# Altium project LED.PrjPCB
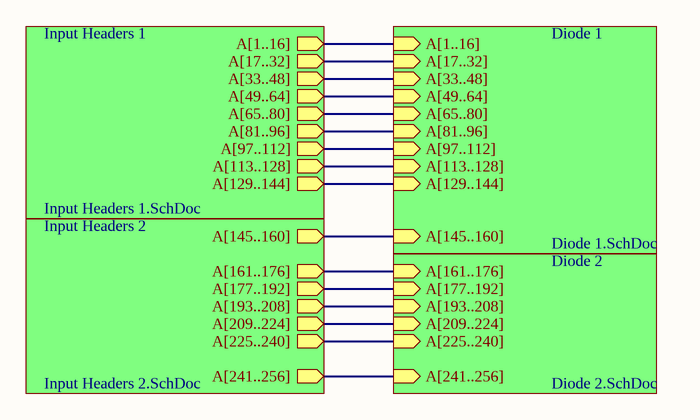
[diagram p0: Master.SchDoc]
5 sheets, 272 parts. Net scope: hierarchical (ports join the sheet entries above them; power ports are global).
Board file: LED Board.PcbDoc
Sheets:
  Master.SchDoc
    Input Headers 1 = Input Headers 1.SchDoc
    Input Headers 2 = Input Headers 2.SchDoc
    Diode 1 = Diode 1.SchDoc
    Diode 2 = Diode 2.SchDoc

## Sheet Master.SchDoc
size A

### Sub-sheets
Diode 1 = Diode 1.SchDoc: A[1..16] (in), A[17..32] (in), A[33..48] (in), A[49..64] (in), A[65..80] (in), A[145..160] (in), A[81..96] (in), A[97..112] (in), A[113..128] (in), A[129..144] (in)
Diode 2 = Diode 2.SchDoc: A[225..240] (in), A[161..176] (in), A[177..192] (in), A[193..208] (in), A[209..224] (in), A[241..256] (in)
Input Headers 1 = Input Headers 1.SchDoc: A[1..16] (out), A[17..32] (out), A[33..48] (out), A[49..64] (out), A[65..80] (out), A[81..96] (out), A[97..112] (out), A[113..128] (out), A[129..144] (out)
Input Headers 2 = Input Headers 2.SchDoc: A[145..160] (out), A[225..240] (out), A[161..176] (out), A[177..192] (out), A[193..208] (out), A[209..224] (out), A[241..256] (out)

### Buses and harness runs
bus sheet Diode 1/A[1..16] = sheet Input Headers 1/A[1..16]
bus sheet Diode 1/A[17..32] = sheet Input Headers 1/A[17..32]
bus sheet Diode 1/A[33..48] = sheet Input Headers 1/A[33..48]
bus sheet Diode 1/A[49..64] = sheet Input Headers 1/A[49..64]
bus sheet Diode 1/A[65..80] = sheet Input Headers 1/A[65..80]
bus sheet Diode 1/A[81..96] = sheet Input Headers 1/A[81..96]
bus sheet Diode 1/A[97..112] = sheet Input Headers 1/A[97..112]
bus sheet Diode 1/A[113..128] = sheet Input Headers 1/A[113..128]
bus sheet Diode 1/A[129..144] = sheet Input Headers 1/A[129..144]
bus sheet Diode 1/A[145..160] = sheet Input Headers 2/A[145..160]
bus sheet Diode 2/A[161..176] = sheet Input Headers 2/A[161..176]
bus sheet Diode 2/A[177..192] = sheet Input Headers 2/A[177..192]
bus sheet Diode 2/A[193..208] = sheet Input Headers 2/A[193..208]
bus sheet Diode 2/A[209..224] = sheet Input Headers 2/A[209..224]
bus sheet Diode 2/A[225..240] = sheet Input Headers 2/A[225..240]
bus sheet Diode 2/A[241..256] = sheet Input Headers 2/A[241..256]

## Sheet Input Headers 1.SchDoc: Input Headers 1
size A; DocumentNumber: 1; SheetNumber: 4
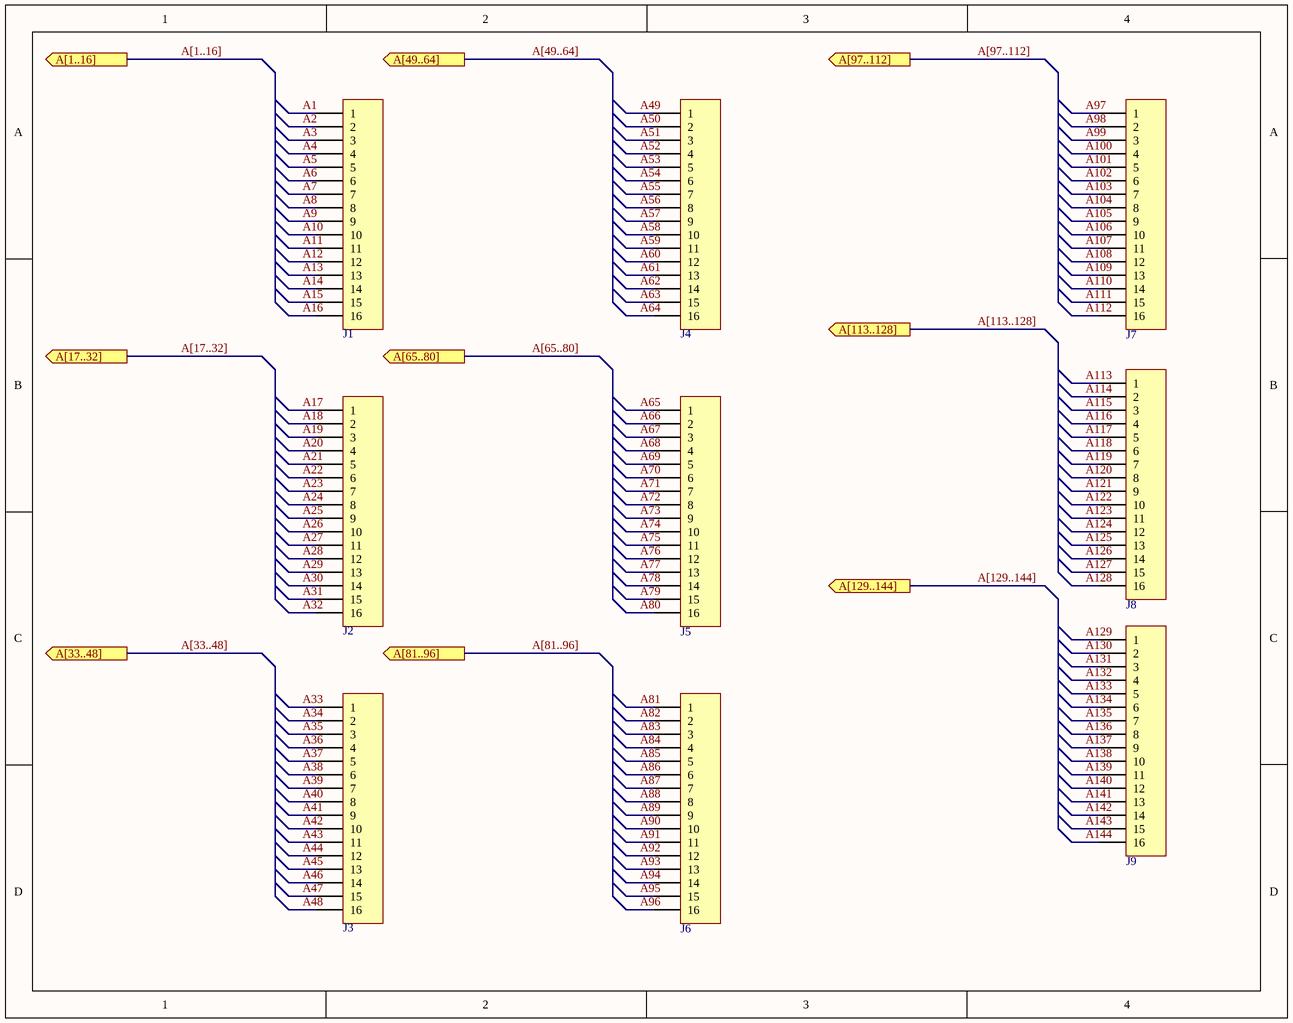
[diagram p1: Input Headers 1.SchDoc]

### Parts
J1  HDR2X8  [HDR2X8]  (value not drawn)
J2  HDR2X8  [HDR2X8]  (value not drawn)
J3  HDR2X8  [HDR2X8]  (value not drawn)
J4  HDR2X8  [HDR2X8]  (value not drawn)
J5  HDR2X8  [HDR2X8]  (value not drawn)
J6  HDR2X8  [HDR2X8]  (value not drawn)
J7  HDR2X8  [HDR2X8]  (value not drawn)
J8  HDR2X8  [HDR2X8]  (value not drawn)
J9  HDR2X8  [HDR2X8]  (value not drawn)

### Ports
A[1..16] (out), A[17..32] (out), A[33..48] (out), A[49..64] (out), A[65..80] (out), A[81..96] (out), A[97..112] (out), A[113..128] (out), A[129..144] (out)

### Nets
A1: J1.1
A2: J1.2
A3: J1.3
A4: J1.4
A5: J1.5
A6: J1.6
A7: J1.7
A8: J1.8
A9: J1.9
A10: J1.10
A11: J1.11
A12: J1.12
A13: J1.13
A14: J1.14
A15: J1.15
A16: J1.16
A17: J2.1
A18: J2.2
A19: J2.3
A20: J2.4
A21: J2.5
A22: J2.6
A23: J2.7
A24: J2.8
A25: J2.9
A26: J2.10
A27: J2.11
A28: J2.12
A29: J2.13
A30: J2.14
A31: J2.15
A32: J2.16
A33: J3.1
A34: J3.2
A35: J3.3
A36: J3.4
A37: J3.5
A38: J3.6
A39: J3.7
A40: J3.8
A41: J3.9
A42: J3.10
A43: J3.11
A44: J3.12
A45: J3.13
A46: J3.14
A47: J3.15
A48: J3.16
A49: J4.1
A50: J4.2
A51: J4.3
A52: J4.4
A53: J4.5
A54: J4.6
A55: J4.7
A56: J4.8
A57: J4.9
A58: J4.10
A59: J4.11
A60: J4.12
A61: J4.13
A62: J4.14
A63: J4.15
A64: J4.16
A65: J5.1
A66: J5.2
A67: J5.3
A68: J5.4
A69: J5.5
A70: J5.6
A71: J5.7
A72: J5.8
A73: J5.9
A74: J5.10
A75: J5.11
A76: J5.12
A77: J5.13
A78: J5.14
A79: J5.15
A80: J5.16
A81: J6.1
A82: J6.2
A83: J6.3
A84: J6.4
A85: J6.5
A86: J6.6
A87: J6.7
A88: J6.8
A89: J6.9
A90: J6.10
A91: J6.11
A92: J6.12
A93: J6.13
A94: J6.14
A95: J6.15
A96: J6.16
A97: J7.1
A98: J7.2
A99: J7.3
A100: J7.4
A101: J7.5
A102: J7.6
A103: J7.7
A104: J7.8
A105: J7.9
A106: J7.10
A107: J7.11
A108: J7.12
A109: J7.13
A110: J7.14
A111: J7.15
A112: J7.16
A113: J8.1
A114: J8.2
A115: J8.3
A116: J8.4
A117: J8.5
A118: J8.6
A119: J8.7
A120: J8.8
A121: J8.9
A122: J8.10
A123: J8.11
A124: J8.12
A125: J8.13
A126: J8.14
A127: J8.15
A128: J8.16
A129: J9.1
A130: J9.2
A131: J9.3
A132: J9.4
A133: J9.5
A134: J9.6
A135: J9.7
A136: J9.8
A137: J9.9
A138: J9.10
A139: J9.11
A140: J9.12
A141: J9.13
A142: J9.14
A143: J9.15
A144: J9.16

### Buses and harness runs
bus A[1..16] = port A[1..16]
bus A[17..32] = port A[17..32]
bus A[33..48] = port A[33..48]
bus A[49..64] = port A[49..64]
bus A[65..80] = port A[65..80]
bus A[81..96] = port A[81..96]
bus A[97..112] = port A[97..112]
bus A[113..128] = port A[113..128]
bus A[129..144] = port A[129..144]

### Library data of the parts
J1-J9 = MHDR1X16: Header, 16-Pin; Manufacturer: Generic Components; Class I: Connector

## Sheet Input Headers 2.SchDoc: Input Headers 2
size A; DocumentNumber: 1; SheetNumber: 5
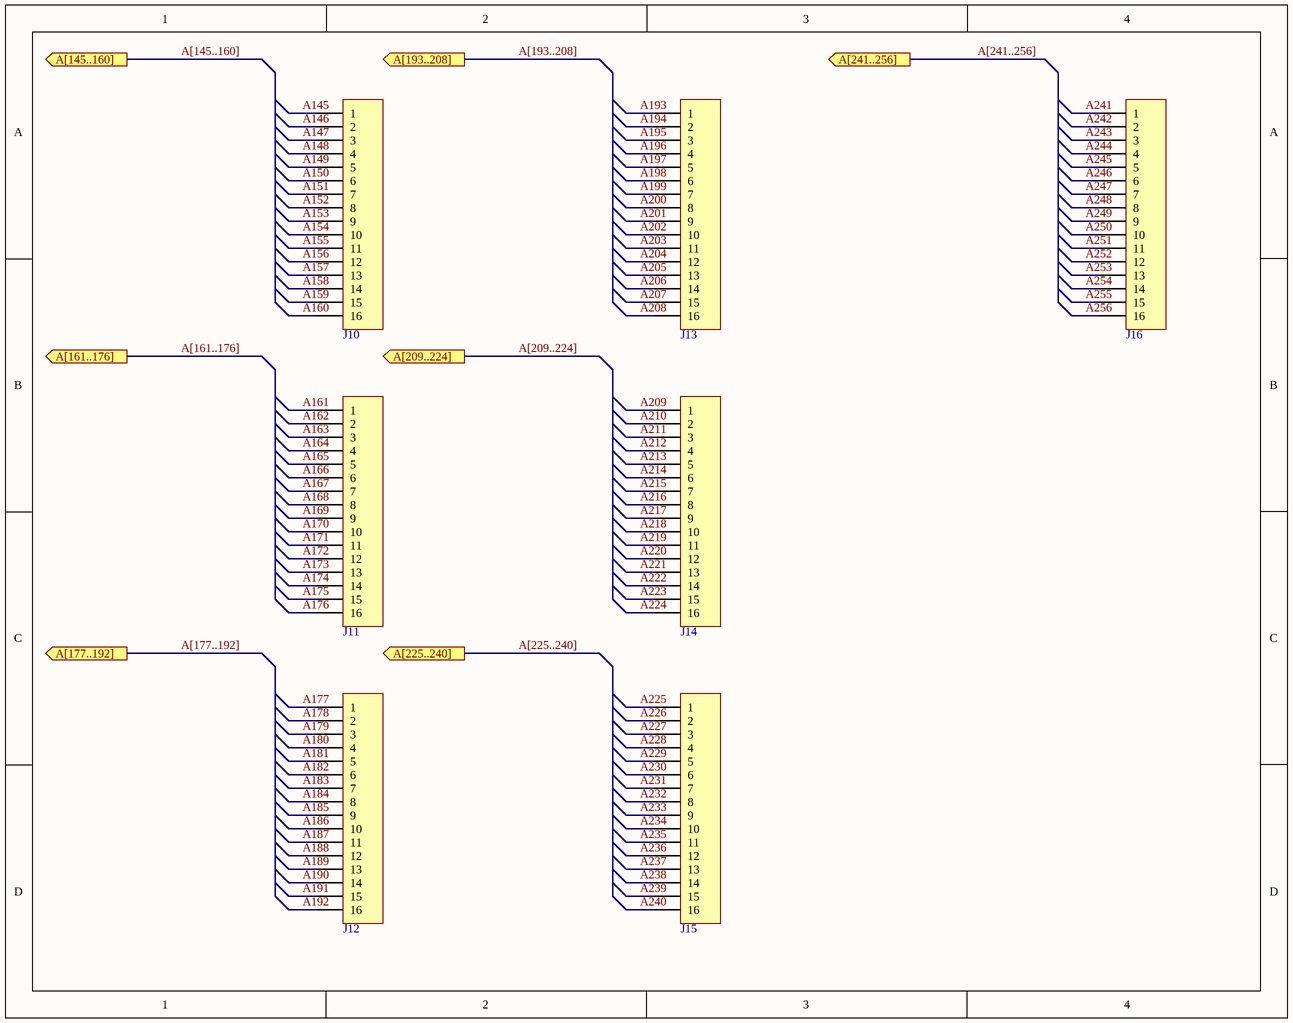
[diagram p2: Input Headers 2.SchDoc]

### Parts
J10  HDR2X8  [HDR2X8]  (value not drawn)
J11  HDR2X8  [HDR2X8]  (value not drawn)
J12  HDR2X8  [HDR2X8]  (value not drawn)
J13  HDR2X8  [HDR2X8]  (value not drawn)
J14  HDR2X8  [HDR2X8]  (value not drawn)
J15  HDR2X8  [HDR2X8]  (value not drawn)
J16  HDR2X8  [HDR2X8]  (value not drawn)

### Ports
A[145..160] (out), A[161..176] (out), A[177..192] (out), A[193..208] (out), A[209..224] (out), A[225..240] (out), A[241..256] (out)

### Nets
A145: J10.1
A146: J10.2
A147: J10.3
A148: J10.4
A149: J10.5
A150: J10.6
A151: J10.7
A152: J10.8
A153: J10.9
A154: J10.10
A155: J10.11
A156: J10.12
A157: J10.13
A158: J10.14
A159: J10.15
A160: J10.16
A161: J11.1
A162: J11.2
A163: J11.3
A164: J11.4
A165: J11.5
A166: J11.6
A167: J11.7
A168: J11.8
A169: J11.9
A170: J11.10
A171: J11.11
A172: J11.12
A173: J11.13
A174: J11.14
A175: J11.15
A176: J11.16
A177: J12.1
A178: J12.2
A179: J12.3
A180: J12.4
A181: J12.5
A182: J12.6
A183: J12.7
A184: J12.8
A185: J12.9
A186: J12.10
A187: J12.11
A188: J12.12
A189: J12.13
A190: J12.14
A191: J12.15
A192: J12.16
A193: J13.1
A194: J13.2
A195: J13.3
A196: J13.4
A197: J13.5
A198: J13.6
A199: J13.7
A200: J13.8
A201: J13.9
A202: J13.10
A203: J13.11
A204: J13.12
A205: J13.13
A206: J13.14
A207: J13.15
A208: J13.16
A209: J14.1
A210: J14.2
A211: J14.3
A212: J14.4
A213: J14.5
A214: J14.6
A215: J14.7
A216: J14.8
A217: J14.9
A218: J14.10
A219: J14.11
A220: J14.12
A221: J14.13
A222: J14.14
A223: J14.15
A224: J14.16
A225: J15.1
A226: J15.2
A227: J15.3
A228: J15.4
A229: J15.5
A230: J15.6
A231: J15.7
A232: J15.8
A233: J15.9
A234: J15.10
A235: J15.11
A236: J15.12
A237: J15.13
A238: J15.14
A239: J15.15
A240: J15.16
A241: J16.1
A242: J16.2
A243: J16.3
A244: J16.4
A245: J16.5
A246: J16.6
A247: J16.7
A248: J16.8
A249: J16.9
A250: J16.10
A251: J16.11
A252: J16.12
A253: J16.13
A254: J16.14
A255: J16.15
A256: J16.16

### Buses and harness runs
bus A[145..160] = port A[145..160]
bus A[161..176] = port A[161..176]
bus A[177..192] = port A[177..192]
bus A[193..208] = port A[193..208]
bus A[209..224] = port A[209..224]
bus A[225..240] = port A[225..240]
bus A[241..256] = port A[241..256]

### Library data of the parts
J10-J16 = MHDR1X16: as J1 on sheet Input Headers 1

## Sheet Diode 1.SchDoc: LED Connections 1
size A; DocumentNumber: 1; SheetNumber: 2
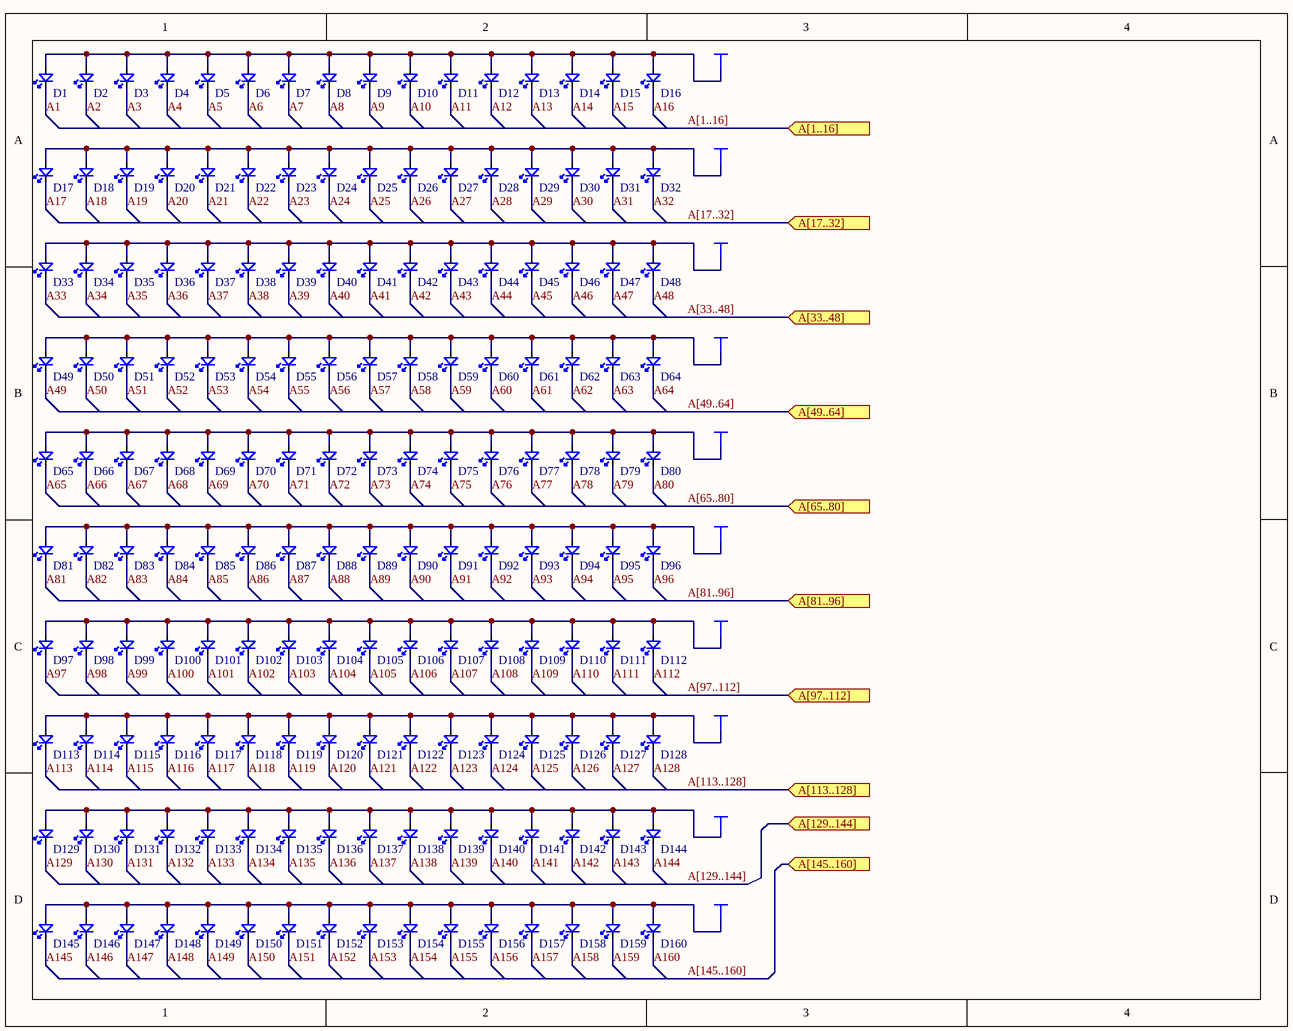
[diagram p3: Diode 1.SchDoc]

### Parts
D1  LED  [LED]  (value not drawn)
D2  LED  [LED]  (value not drawn)
D3  LED  [LED]  (value not drawn)
D4  LED  [LED]  (value not drawn)
D5  LED  [LED]  (value not drawn)
D6  LED  [LED]  (value not drawn)
D7  LED  [LED]  (value not drawn)
D8  LED  [LED]  (value not drawn)
D9  LED  [LED]  (value not drawn)
D10  LED  [LED]  (value not drawn)
D11  LED  [LED]  (value not drawn)
D12  LED  [LED]  (value not drawn)
D13  LED  [LED]  (value not drawn)
D14  LED  [LED]  (value not drawn)
D15  LED  [LED]  (value not drawn)
D16  LED  [LED]  (value not drawn)
D17  LED  [LED]  (value not drawn)
D18  LED  [LED]  (value not drawn)
D19  LED  [LED]  (value not drawn)
D20  LED  [LED]  (value not drawn)
D21  LED  [LED]  (value not drawn)
D22  LED  [LED]  (value not drawn)
D23  LED  [LED]  (value not drawn)
D24  LED  [LED]  (value not drawn)
D25  LED  [LED]  (value not drawn)
D26  LED  [LED]  (value not drawn)
D27  LED  [LED]  (value not drawn)
D28  LED  [LED]  (value not drawn)
D29  LED  [LED]  (value not drawn)
D30  LED  [LED]  (value not drawn)
D31  LED  [LED]  (value not drawn)
D32  LED  [LED]  (value not drawn)
D33  LED  [LED]  (value not drawn)
D34  LED  [LED]  (value not drawn)
D35  LED  [LED]  (value not drawn)
D36  LED  [LED]  (value not drawn)
D37  LED  [LED]  (value not drawn)
D38  LED  [LED]  (value not drawn)
D39  LED  [LED]  (value not drawn)
D40  LED  [LED]  (value not drawn)
D41  LED  [LED]  (value not drawn)
D42  LED  [LED]  (value not drawn)
D43  LED  [LED]  (value not drawn)
D44  LED  [LED]  (value not drawn)
D45  LED  [LED]  (value not drawn)
D46  LED  [LED]  (value not drawn)
D47  LED  [LED]  (value not drawn)
D48  LED  [LED]  (value not drawn)
D49  LED  [LED]  (value not drawn)
D50  LED  [LED]  (value not drawn)
D51  LED  [LED]  (value not drawn)
D52  LED  [LED]  (value not drawn)
D53  LED  [LED]  (value not drawn)
D54  LED  [LED]  (value not drawn)
D55  LED  [LED]  (value not drawn)
D56  LED  [LED]  (value not drawn)
D57  LED  [LED]  (value not drawn)
D58  LED  [LED]  (value not drawn)
D59  LED  [LED]  (value not drawn)
D60  LED  [LED]  (value not drawn)
D61  LED  [LED]  (value not drawn)
D62  LED  [LED]  (value not drawn)
D63  LED  [LED]  (value not drawn)
D64  LED  [LED]  (value not drawn)
D65  LED  [LED]  (value not drawn)
D66  LED  [LED]  (value not drawn)
D67  LED  [LED]  (value not drawn)
D68  LED  [LED]  (value not drawn)
D69  LED  [LED]  (value not drawn)
D70  LED  [LED]  (value not drawn)
D71  LED  [LED]  (value not drawn)
D72  LED  [LED]  (value not drawn)
D73  LED  [LED]  (value not drawn)
D74  LED  [LED]  (value not drawn)
D75  LED  [LED]  (value not drawn)
D76  LED  [LED]  (value not drawn)
D77  LED  [LED]  (value not drawn)
D78  LED  [LED]  (value not drawn)
D79  LED  [LED]  (value not drawn)
D80  LED  [LED]  (value not drawn)
D81  LED  [LED]  (value not drawn)
D82  LED  [LED]  (value not drawn)
D83  LED  [LED]  (value not drawn)
D84  LED  [LED]  (value not drawn)
D85  LED  [LED]  (value not drawn)
D86  LED  [LED]  (value not drawn)
D87  LED  [LED]  (value not drawn)
D88  LED  [LED]  (value not drawn)
D89  LED  [LED]  (value not drawn)
D90  LED  [LED]  (value not drawn)
D91  LED  [LED]  (value not drawn)
D92  LED  [LED]  (value not drawn)
D93  LED  [LED]  (value not drawn)
D94  LED  [LED]  (value not drawn)
D95  LED  [LED]  (value not drawn)
D96  LED  [LED]  (value not drawn)
D97  LED  [LED]  (value not drawn)
D98  LED  [LED]  (value not drawn)
D99  LED  [LED]  (value not drawn)
D100  LED  [LED]  (value not drawn)
D101  LED  [LED]  (value not drawn)
D102  LED  [LED]  (value not drawn)
D103  LED  [LED]  (value not drawn)
D104  LED  [LED]  (value not drawn)
D105  LED  [LED]  (value not drawn)
D106  LED  [LED]  (value not drawn)
D107  LED  [LED]  (value not drawn)
D108  LED  [LED]  (value not drawn)
D109  LED  [LED]  (value not drawn)
D110  LED  [LED]  (value not drawn)
D111  LED  [LED]  (value not drawn)
D112  LED  [LED]  (value not drawn)
D113  LED  [LED]  (value not drawn)
D114  LED  [LED]  (value not drawn)
D115  LED  [LED]  (value not drawn)
D116  LED  [LED]  (value not drawn)
D117  LED  [LED]  (value not drawn)
D118  LED  [LED]  (value not drawn)
D119  LED  [LED]  (value not drawn)
D120  LED  [LED]  (value not drawn)
D121  LED  [LED]  (value not drawn)
D122  LED  [LED]  (value not drawn)
D123  LED  [LED]  (value not drawn)
D124  LED  [LED]  (value not drawn)
D125  LED  [LED]  (value not drawn)
D126  LED  [LED]  (value not drawn)
D127  LED  [LED]  (value not drawn)
D128  LED  [LED]  (value not drawn)
D129  LED  [LED]  (value not drawn)
D130  LED  [LED]  (value not drawn)
D131  LED  [LED]  (value not drawn)
D132  LED  [LED]  (value not drawn)
D133  LED  [LED]  (value not drawn)
D134  LED  [LED]  (value not drawn)
D135  LED  [LED]  (value not drawn)
D136  LED  [LED]  (value not drawn)
D137  LED  [LED]  (value not drawn)
D138  LED  [LED]  (value not drawn)
D139  LED  [LED]  (value not drawn)
D140  LED  [LED]  (value not drawn)
D141  LED  [LED]  (value not drawn)
D142  LED  [LED]  (value not drawn)
D143  LED  [LED]  (value not drawn)
D144  LED  [LED]  (value not drawn)
D145  LED  [LED]  (value not drawn)
D146  LED  [LED]  (value not drawn)
D147  LED  [LED]  (value not drawn)
D148  LED  [LED]  (value not drawn)
D149  LED  [LED]  (value not drawn)
D150  LED  [LED]  (value not drawn)
D151  LED  [LED]  (value not drawn)
D152  LED  [LED]  (value not drawn)
D153  LED  [LED]  (value not drawn)
D154  LED  [LED]  (value not drawn)
D155  LED  [LED]  (value not drawn)
D156  LED  [LED]  (value not drawn)
D157  LED  [LED]  (value not drawn)
D158  LED  [LED]  (value not drawn)
D159  LED  [LED]  (value not drawn)
D160  LED  [LED]  (value not drawn)

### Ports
A[1..16] (in), A[17..32] (in), A[33..48] (in), A[49..64] (in), A[65..80] (in), A[81..96] (in), A[97..112] (in), A[113..128] (in), A[129..144] (in), A[145..160] (in)

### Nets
+5: D1.1(A) D2.1(A) D3.1(A) D4.1(A) D5.1(A) D6.1(A) D7.1(A) D8.1(A) D9.1(A) D10.1(A) D11.1(A) D12.1(A) D13.1(A) D14.1(A) D15.1(A) D16.1(A) D17.1(A) D18.1(A) D19.1(A) D20.1(A) D21.1(A) D22.1(A) D23.1(A) D24.1(A) D25.1(A) D26.1(A) D27.1(A) D28.1(A) D29.1(A) D30.1(A) D31.1(A) D32.1(A) D33.1(A) D34.1(A) D35.1(A) D36.1(A) D37.1(A) D38.1(A) D39.1(A) D40.1(A) D41.1(A) D42.1(A) D43.1(A) D44.1(A) D45.1(A) D46.1(A) D47.1(A) D48.1(A) D49.1(A) D50.1(A) D51.1(A) D52.1(A) D53.1(A) D54.1(A) D55.1(A) D56.1(A) D57.1(A) D58.1(A) D59.1(A) D60.1(A) D61.1(A) D62.1(A) D63.1(A) D64.1(A) D65.1(A) D66.1(A) D67.1(A) D68.1(A) D69.1(A) D70.1(A) D71.1(A) D72.1(A) D73.1(A) D74.1(A) D75.1(A) D76.1(A) D77.1(A) D78.1(A) D79.1(A) D80.1(A) D81.1(A) D82.1(A) D83.1(A) D84.1(A) D85.1(A) D86.1(A) D87.1(A) D88.1(A) D89.1(A) D90.1(A) D91.1(A) D92.1(A) D93.1(A) D94.1(A) D95.1(A) D96.1(A) D97.1(A) D98.1(A) D99.1(A) D100.1(A) D101.1(A) D102.1(A) D103.1(A) D104.1(A) D105.1(A) D106.1(A) D107.1(A) D108.1(A) D109.1(A) D110.1(A) D111.1(A) D112.1(A) D113.1(A) D114.1(A) D115.1(A) D116.1(A) D117.1(A) D118.1(A) D119.1(A) D120.1(A) D121.1(A) D122.1(A) D123.1(A) D124.1(A) D125.1(A) D126.1(A) D127.1(A) D128.1(A) D129.1(A) D130.1(A) D131.1(A) D132.1(A) D133.1(A) D134.1(A) D135.1(A) D136.1(A) D137.1(A) D138.1(A) D139.1(A) D140.1(A) D141.1(A) D142.1(A) D143.1(A) D144.1(A) D145.1(A) D146.1(A) D147.1(A) D148.1(A) D149.1(A) D150.1(A) D151.1(A) D152.1(A) D153.1(A) D154.1(A) D155.1(A) D156.1(A) D157.1(A) D158.1(A) D159.1(A) D160.1(A)
A1: D1.2(K)
A2: D2.2(K)
A3: D3.2(K)
A4: D4.2(K)
A5: D5.2(K)
A6: D6.2(K)
A7: D7.2(K)
A8: D8.2(K)
A9: D9.2(K)
A10: D10.2(K)
A11: D11.2(K)
A12: D12.2(K)
A13: D13.2(K)
A14: D14.2(K)
A15: D15.2(K)
A16: D16.2(K)
A17: D17.2(K)
A18: D18.2(K)
A19: D19.2(K)
A20: D20.2(K)
A21: D21.2(K)
A22: D22.2(K)
A23: D23.2(K)
A24: D24.2(K)
A25: D25.2(K)
A26: D26.2(K)
A27: D27.2(K)
A28: D28.2(K)
A29: D29.2(K)
A30: D30.2(K)
A31: D31.2(K)
A32: D32.2(K)
A33: D33.2(K)
A34: D34.2(K)
A35: D35.2(K)
A36: D36.2(K)
A37: D37.2(K)
A38: D38.2(K)
A39: D39.2(K)
A40: D40.2(K)
A41: D41.2(K)
A42: D42.2(K)
A43: D43.2(K)
A44: D44.2(K)
A45: D45.2(K)
A46: D46.2(K)
A47: D47.2(K)
A48: D48.2(K)
A49: D49.2(K)
A50: D50.2(K)
A51: D51.2(K)
A52: D52.2(K)
A53: D53.2(K)
A54: D54.2(K)
A55: D55.2(K)
A56: D56.2(K)
A57: D57.2(K)
A58: D58.2(K)
A59: D59.2(K)
A60: D60.2(K)
A61: D61.2(K)
A62: D62.2(K)
A63: D63.2(K)
A64: D64.2(K)
A65: D65.2(K)
A66: D66.2(K)
A67: D67.2(K)
A68: D68.2(K)
A69: D69.2(K)
A70: D70.2(K)
A71: D71.2(K)
A72: D72.2(K)
A73: D73.2(K)
A74: D74.2(K)
A75: D75.2(K)
A76: D76.2(K)
A77: D77.2(K)
A78: D78.2(K)
A79: D79.2(K)
A80: D80.2(K)
A81: D81.2(K)
A82: D82.2(K)
A83: D83.2(K)
A84: D84.2(K)
A85: D85.2(K)
A86: D86.2(K)
A87: D87.2(K)
A88: D88.2(K)
A89: D89.2(K)
A90: D90.2(K)
A91: D91.2(K)
A92: D92.2(K)
A93: D93.2(K)
A94: D94.2(K)
A95: D95.2(K)
A96: D96.2(K)
A97: D97.2(K)
A98: D98.2(K)
A99: D99.2(K)
A100: D100.2(K)
A101: D101.2(K)
A102: D102.2(K)
A103: D103.2(K)
A104: D104.2(K)
A105: D105.2(K)
A106: D106.2(K)
A107: D107.2(K)
A108: D108.2(K)
A109: D109.2(K)
A110: D110.2(K)
A111: D111.2(K)
A112: D112.2(K)
A113: D113.2(K)
A114: D114.2(K)
A115: D115.2(K)
A116: D116.2(K)
A117: D117.2(K)
A118: D118.2(K)
A119: D119.2(K)
A120: D120.2(K)
A121: D121.2(K)
A122: D122.2(K)
A123: D123.2(K)
A124: D124.2(K)
A125: D125.2(K)
A126: D126.2(K)
A127: D127.2(K)
A128: D128.2(K)
A129: D129.2(K)
A130: D130.2(K)
A131: D131.2(K)
A132: D132.2(K)
A133: D133.2(K)
A134: D134.2(K)
A135: D135.2(K)
A136: D136.2(K)
A137: D137.2(K)
A138: D138.2(K)
A139: D139.2(K)
A140: D140.2(K)
A141: D141.2(K)
A142: D142.2(K)
A143: D143.2(K)
A144: D144.2(K)
A145: D145.2(K)
A146: D146.2(K)
A147: D147.2(K)
A148: D148.2(K)
A149: D149.2(K)
A150: D150.2(K)
A151: D151.2(K)
A152: D152.2(K)
A153: D153.2(K)
A154: D154.2(K)
A155: D155.2(K)
A156: D156.2(K)
A157: D157.2(K)
A158: D158.2(K)
A159: D159.2(K)
A160: D160.2(K)

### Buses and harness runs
bus A[1..16] = port A[1..16]
bus A[17..32] = port A[17..32]
bus A[33..48] = port A[33..48]
bus A[49..64] = port A[49..64]
bus A[65..80] = port A[65..80]
bus A[81..96] = port A[81..96]
bus A[97..112] = port A[97..112]
bus A[113..128] = port A[113..128]
bus A[129..144] = port A[129..144]
bus A[145..160] = port A[145..160]

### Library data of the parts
D1-D160 = LED1: Typical RED GaAs LED; Manufacturer: Generic Components; Class I: Optoelectronic

## Sheet Diode 2.SchDoc: LED Connections 2
size A; DocumentNumber: 1; SheetNumber: 3
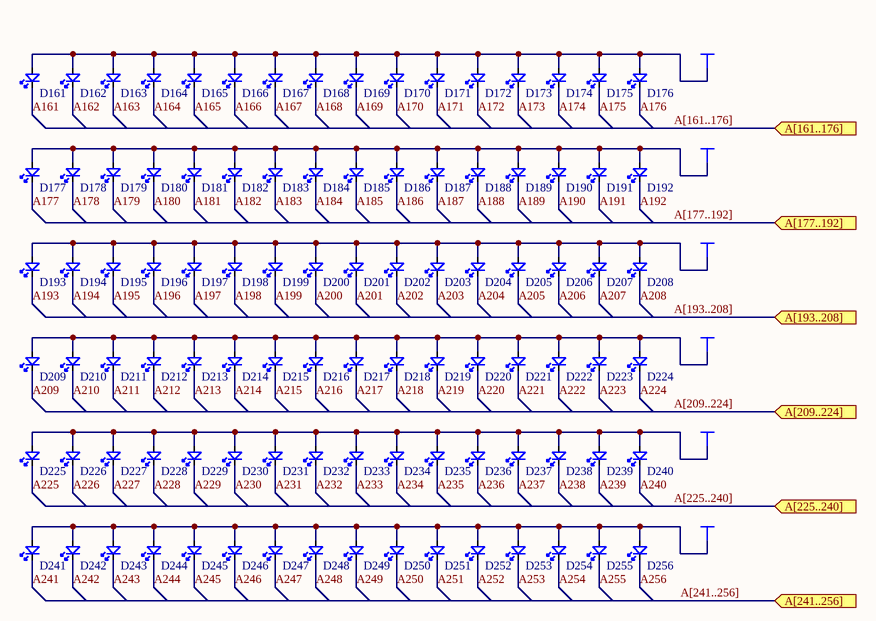
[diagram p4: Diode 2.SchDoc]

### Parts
D161  LED  [LED]  (value not drawn)
D162  LED  [LED]  (value not drawn)
D163  LED  [LED]  (value not drawn)
D164  LED  [LED]  (value not drawn)
D165  LED  [LED]  (value not drawn)
D166  LED  [LED]  (value not drawn)
D167  LED  [LED]  (value not drawn)
D168  LED  [LED]  (value not drawn)
D169  LED  [LED]  (value not drawn)
D170  LED  [LED]  (value not drawn)
D171  LED  [LED]  (value not drawn)
D172  LED  [LED]  (value not drawn)
D173  LED  [LED]  (value not drawn)
D174  LED  [LED]  (value not drawn)
D175  LED  [LED]  (value not drawn)
D176  LED  [LED]  (value not drawn)
D177  LED  [LED]  (value not drawn)
D178  LED  [LED]  (value not drawn)
D179  LED  [LED]  (value not drawn)
D180  LED  [LED]  (value not drawn)
D181  LED  [LED]  (value not drawn)
D182  LED  [LED]  (value not drawn)
D183  LED  [LED]  (value not drawn)
D184  LED  [LED]  (value not drawn)
D185  LED  [LED]  (value not drawn)
D186  LED  [LED]  (value not drawn)
D187  LED  [LED]  (value not drawn)
D188  LED  [LED]  (value not drawn)
D189  LED  [LED]  (value not drawn)
D190  LED  [LED]  (value not drawn)
D191  LED  [LED]  (value not drawn)
D192  LED  [LED]  (value not drawn)
D193  LED  [LED]  (value not drawn)
D194  LED  [LED]  (value not drawn)
D195  LED  [LED]  (value not drawn)
D196  LED  [LED]  (value not drawn)
D197  LED  [LED]  (value not drawn)
D198  LED  [LED]  (value not drawn)
D199  LED  [LED]  (value not drawn)
D200  LED  [LED]  (value not drawn)
D201  LED  [LED]  (value not drawn)
D202  LED  [LED]  (value not drawn)
D203  LED  [LED]  (value not drawn)
D204  LED  [LED]  (value not drawn)
D205  LED  [LED]  (value not drawn)
D206  LED  [LED]  (value not drawn)
D207  LED  [LED]  (value not drawn)
D208  LED  [LED]  (value not drawn)
D209  LED  [LED]  (value not drawn)
D210  LED  [LED]  (value not drawn)
D211  LED  [LED]  (value not drawn)
D212  LED  [LED]  (value not drawn)
D213  LED  [LED]  (value not drawn)
D214  LED  [LED]  (value not drawn)
D215  LED  [LED]  (value not drawn)
D216  LED  [LED]  (value not drawn)
D217  LED  [LED]  (value not drawn)
D218  LED  [LED]  (value not drawn)
D219  LED  [LED]  (value not drawn)
D220  LED  [LED]  (value not drawn)
D221  LED  [LED]  (value not drawn)
D222  LED  [LED]  (value not drawn)
D223  LED  [LED]  (value not drawn)
D224  LED  [LED]  (value not drawn)
D225  LED  [LED]  (value not drawn)
D226  LED  [LED]  (value not drawn)
D227  LED  [LED]  (value not drawn)
D228  LED  [LED]  (value not drawn)
D229  LED  [LED]  (value not drawn)
D230  LED  [LED]  (value not drawn)
D231  LED  [LED]  (value not drawn)
D232  LED  [LED]  (value not drawn)
D233  LED  [LED]  (value not drawn)
D234  LED  [LED]  (value not drawn)
D235  LED  [LED]  (value not drawn)
D236  LED  [LED]  (value not drawn)
D237  LED  [LED]  (value not drawn)
D238  LED  [LED]  (value not drawn)
D239  LED  [LED]  (value not drawn)
D240  LED  [LED]  (value not drawn)
D241  LED  [LED]  (value not drawn)
D242  LED  [LED]  (value not drawn)
D243  LED  [LED]  (value not drawn)
D244  LED  [LED]  (value not drawn)
D245  LED  [LED]  (value not drawn)
D246  LED  [LED]  (value not drawn)
D247  LED  [LED]  (value not drawn)
D248  LED  [LED]  (value not drawn)
D249  LED  [LED]  (value not drawn)
D250  LED  [LED]  (value not drawn)
D251  LED  [LED]  (value not drawn)
D252  LED  [LED]  (value not drawn)
D253  LED  [LED]  (value not drawn)
D254  LED  [LED]  (value not drawn)
D255  LED  [LED]  (value not drawn)
D256  LED  [LED]  (value not drawn)

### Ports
A[161..176] (in), A[177..192] (in), A[193..208] (in), A[209..224] (in), A[225..240] (in), A[241..256] (in)

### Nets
+5: D161.1(A) D162.1(A) D163.1(A) D164.1(A) D165.1(A) D166.1(A) D167.1(A) D168.1(A) D169.1(A) D170.1(A) D171.1(A) D172.1(A) D173.1(A) D174.1(A) D175.1(A) D176.1(A) D177.1(A) D178.1(A) D179.1(A) D180.1(A) D181.1(A) D182.1(A) D183.1(A) D184.1(A) D185.1(A) D186.1(A) D187.1(A) D188.1(A) D189.1(A) D190.1(A) D191.1(A) D192.1(A) D193.1(A) D194.1(A) D195.1(A) D196.1(A) D197.1(A) D198.1(A) D199.1(A) D200.1(A) D201.1(A) D202.1(A) D203.1(A) D204.1(A) D205.1(A) D206.1(A) D207.1(A) D208.1(A) D209.1(A) D210.1(A) D211.1(A) D212.1(A) D213.1(A) D214.1(A) D215.1(A) D216.1(A) D217.1(A) D218.1(A) D219.1(A) D220.1(A) D221.1(A) D222.1(A) D223.1(A) D224.1(A) D225.1(A) D226.1(A) D227.1(A) D228.1(A) D229.1(A) D230.1(A) D231.1(A) D232.1(A) D233.1(A) D234.1(A) D235.1(A) D236.1(A) D237.1(A) D238.1(A) D239.1(A) D240.1(A) D241.1(A) D242.1(A) D243.1(A) D244.1(A) D245.1(A) D246.1(A) D247.1(A) D248.1(A) D249.1(A) D250.1(A) D251.1(A) D252.1(A) D253.1(A) D254.1(A) D255.1(A) D256.1(A)
A161: D161.2(K)
A162: D162.2(K)
A163: D163.2(K)
A164: D164.2(K)
A165: D165.2(K)
A166: D166.2(K)
A167: D167.2(K)
A168: D168.2(K)
A169: D169.2(K)
A170: D170.2(K)
A171: D171.2(K)
A172: D172.2(K)
A173: D173.2(K)
A174: D174.2(K)
A175: D175.2(K)
A176: D176.2(K)
A177: D177.2(K)
A178: D178.2(K)
A179: D179.2(K)
A180: D180.2(K)
A181: D181.2(K)
A182: D182.2(K)
A183: D183.2(K)
A184: D184.2(K)
A185: D185.2(K)
A186: D186.2(K)
A187: D187.2(K)
A188: D188.2(K)
A189: D189.2(K)
A190: D190.2(K)
A191: D191.2(K)
A192: D192.2(K)
A193: D193.2(K)
A194: D194.2(K)
A195: D195.2(K)
A196: D196.2(K)
A197: D197.2(K)
A198: D198.2(K)
A199: D199.2(K)
A200: D200.2(K)
A201: D201.2(K)
A202: D202.2(K)
A203: D203.2(K)
A204: D204.2(K)
A205: D205.2(K)
A206: D206.2(K)
A207: D207.2(K)
A208: D208.2(K)
A209: D209.2(K)
A210: D210.2(K)
A211: D211.2(K)
A212: D212.2(K)
A213: D213.2(K)
A214: D214.2(K)
A215: D215.2(K)
A216: D216.2(K)
A217: D217.2(K)
A218: D218.2(K)
A219: D219.2(K)
A220: D220.2(K)
A221: D221.2(K)
A222: D222.2(K)
A223: D223.2(K)
A224: D224.2(K)
A225: D225.2(K)
A226: D226.2(K)
A227: D227.2(K)
A228: D228.2(K)
A229: D229.2(K)
A230: D230.2(K)
A231: D231.2(K)
A232: D232.2(K)
A233: D233.2(K)
A234: D234.2(K)
A235: D235.2(K)
A236: D236.2(K)
A237: D237.2(K)
A238: D238.2(K)
A239: D239.2(K)
A240: D240.2(K)
A241: D241.2(K)
A242: D242.2(K)
A243: D243.2(K)
A244: D244.2(K)
A245: D245.2(K)
A246: D246.2(K)
A247: D247.2(K)
A248: D248.2(K)
A249: D249.2(K)
A250: D250.2(K)
A251: D251.2(K)
A252: D252.2(K)
A253: D253.2(K)
A254: D254.2(K)
A255: D255.2(K)
A256: D256.2(K)

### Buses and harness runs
bus A[161..176] = port A[161..176]
bus A[177..192] = port A[177..192]
bus A[193..208] = port A[193..208]
bus A[209..224] = port A[209..224]
bus A[225..240] = port A[225..240]
bus A[241..256] = port A[241..256]

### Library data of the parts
D161-D256 = LED1: as D1 on sheet Diode 1

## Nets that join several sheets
+5: Diode 1 (160 pins), Diode 2 (96 pins)
A1: Input Headers 1 (J1.1), Diode 1 (D1.2)
A2: Input Headers 1 (J1.2), Diode 1 (D2.2)
A3: Input Headers 1 (J1.3), Diode 1 (D3.2)
A4: Input Headers 1 (J1.4), Diode 1 (D4.2)
A5: Input Headers 1 (J1.5), Diode 1 (D5.2)
A6: Input Headers 1 (J1.6), Diode 1 (D6.2)
A7: Input Headers 1 (J1.7), Diode 1 (D7.2)
A8: Input Headers 1 (J1.8), Diode 1 (D8.2)
A9: Input Headers 1 (J1.9), Diode 1 (D9.2)
A10: Input Headers 1 (J1.10), Diode 1 (D10.2)
A11: Input Headers 1 (J1.11), Diode 1 (D11.2)
A12: Input Headers 1 (J1.12), Diode 1 (D12.2)
A13: Input Headers 1 (J1.13), Diode 1 (D13.2)
A14: Input Headers 1 (J1.14), Diode 1 (D14.2)
A15: Input Headers 1 (J1.15), Diode 1 (D15.2)
A16: Input Headers 1 (J1.16), Diode 1 (D16.2)
A17: Input Headers 1 (J2.1), Diode 1 (D17.2)
A18: Input Headers 1 (J2.2), Diode 1 (D18.2)
A19: Input Headers 1 (J2.3), Diode 1 (D19.2)
A20: Input Headers 1 (J2.4), Diode 1 (D20.2)
A21: Input Headers 1 (J2.5), Diode 1 (D21.2)
A22: Input Headers 1 (J2.6), Diode 1 (D22.2)
A23: Input Headers 1 (J2.7), Diode 1 (D23.2)
A24: Input Headers 1 (J2.8), Diode 1 (D24.2)
A25: Input Headers 1 (J2.9), Diode 1 (D25.2)
A26: Input Headers 1 (J2.10), Diode 1 (D26.2)
A27: Input Headers 1 (J2.11), Diode 1 (D27.2)
A28: Input Headers 1 (J2.12), Diode 1 (D28.2)
A29: Input Headers 1 (J2.13), Diode 1 (D29.2)
A30: Input Headers 1 (J2.14), Diode 1 (D30.2)
A31: Input Headers 1 (J2.15), Diode 1 (D31.2)
A32: Input Headers 1 (J2.16), Diode 1 (D32.2)
A33: Input Headers 1 (J3.1), Diode 1 (D33.2)
A34: Input Headers 1 (J3.2), Diode 1 (D34.2)
A35: Input Headers 1 (J3.3), Diode 1 (D35.2)
A36: Input Headers 1 (J3.4), Diode 1 (D36.2)
A37: Input Headers 1 (J3.5), Diode 1 (D37.2)
A38: Input Headers 1 (J3.6), Diode 1 (D38.2)
A39: Input Headers 1 (J3.7), Diode 1 (D39.2)
A40: Input Headers 1 (J3.8), Diode 1 (D40.2)
A41: Input Headers 1 (J3.9), Diode 1 (D41.2)
A42: Input Headers 1 (J3.10), Diode 1 (D42.2)
A43: Input Headers 1 (J3.11), Diode 1 (D43.2)
A44: Input Headers 1 (J3.12), Diode 1 (D44.2)
A45: Input Headers 1 (J3.13), Diode 1 (D45.2)
A46: Input Headers 1 (J3.14), Diode 1 (D46.2)
A47: Input Headers 1 (J3.15), Diode 1 (D47.2)
A48: Input Headers 1 (J3.16), Diode 1 (D48.2)
A49: Input Headers 1 (J4.1), Diode 1 (D49.2)
A50: Input Headers 1 (J4.2), Diode 1 (D50.2)
A51: Input Headers 1 (J4.3), Diode 1 (D51.2)
A52: Input Headers 1 (J4.4), Diode 1 (D52.2)
A53: Input Headers 1 (J4.5), Diode 1 (D53.2)
A54: Input Headers 1 (J4.6), Diode 1 (D54.2)
A55: Input Headers 1 (J4.7), Diode 1 (D55.2)
A56: Input Headers 1 (J4.8), Diode 1 (D56.2)
A57: Input Headers 1 (J4.9), Diode 1 (D57.2)
A58: Input Headers 1 (J4.10), Diode 1 (D58.2)
A59: Input Headers 1 (J4.11), Diode 1 (D59.2)
A60: Input Headers 1 (J4.12), Diode 1 (D60.2)
A61: Input Headers 1 (J4.13), Diode 1 (D61.2)
A62: Input Headers 1 (J4.14), Diode 1 (D62.2)
A63: Input Headers 1 (J4.15), Diode 1 (D63.2)
A64: Input Headers 1 (J4.16), Diode 1 (D64.2)
A65: Input Headers 1 (J5.1), Diode 1 (D65.2)
A66: Input Headers 1 (J5.2), Diode 1 (D66.2)
A67: Input Headers 1 (J5.3), Diode 1 (D67.2)
A68: Input Headers 1 (J5.4), Diode 1 (D68.2)
A69: Input Headers 1 (J5.5), Diode 1 (D69.2)
A70: Input Headers 1 (J5.6), Diode 1 (D70.2)
A71: Input Headers 1 (J5.7), Diode 1 (D71.2)
A72: Input Headers 1 (J5.8), Diode 1 (D72.2)
A73: Input Headers 1 (J5.9), Diode 1 (D73.2)
A74: Input Headers 1 (J5.10), Diode 1 (D74.2)
A75: Input Headers 1 (J5.11), Diode 1 (D75.2)
A76: Input Headers 1 (J5.12), Diode 1 (D76.2)
A77: Input Headers 1 (J5.13), Diode 1 (D77.2)
A78: Input Headers 1 (J5.14), Diode 1 (D78.2)
A79: Input Headers 1 (J5.15), Diode 1 (D79.2)
A80: Input Headers 1 (J5.16), Diode 1 (D80.2)
A81: Input Headers 1 (J6.1), Diode 1 (D81.2)
A82: Input Headers 1 (J6.2), Diode 1 (D82.2)
A83: Input Headers 1 (J6.3), Diode 1 (D83.2)
A84: Input Headers 1 (J6.4), Diode 1 (D84.2)
A85: Input Headers 1 (J6.5), Diode 1 (D85.2)
A86: Input Headers 1 (J6.6), Diode 1 (D86.2)
A87: Input Headers 1 (J6.7), Diode 1 (D87.2)
A88: Input Headers 1 (J6.8), Diode 1 (D88.2)
A89: Input Headers 1 (J6.9), Diode 1 (D89.2)
A90: Input Headers 1 (J6.10), Diode 1 (D90.2)
A91: Input Headers 1 (J6.11), Diode 1 (D91.2)
A92: Input Headers 1 (J6.12), Diode 1 (D92.2)
A93: Input Headers 1 (J6.13), Diode 1 (D93.2)
A94: Input Headers 1 (J6.14), Diode 1 (D94.2)
A95: Input Headers 1 (J6.15), Diode 1 (D95.2)
A96: Input Headers 1 (J6.16), Diode 1 (D96.2)
A97: Input Headers 1 (J7.1), Diode 1 (D97.2)
A98: Input Headers 1 (J7.2), Diode 1 (D98.2)
A99: Input Headers 1 (J7.3), Diode 1 (D99.2)
A100: Input Headers 1 (J7.4), Diode 1 (D100.2)
A101: Input Headers 1 (J7.5), Diode 1 (D101.2)
A102: Input Headers 1 (J7.6), Diode 1 (D102.2)
A103: Input Headers 1 (J7.7), Diode 1 (D103.2)
A104: Input Headers 1 (J7.8), Diode 1 (D104.2)
A105: Input Headers 1 (J7.9), Diode 1 (D105.2)
A106: Input Headers 1 (J7.10), Diode 1 (D106.2)
A107: Input Headers 1 (J7.11), Diode 1 (D107.2)
A108: Input Headers 1 (J7.12), Diode 1 (D108.2)
A109: Input Headers 1 (J7.13), Diode 1 (D109.2)
A110: Input Headers 1 (J7.14), Diode 1 (D110.2)
A111: Input Headers 1 (J7.15), Diode 1 (D111.2)
A112: Input Headers 1 (J7.16), Diode 1 (D112.2)
A113: Input Headers 1 (J8.1), Diode 1 (D113.2)
A114: Input Headers 1 (J8.2), Diode 1 (D114.2)
A115: Input Headers 1 (J8.3), Diode 1 (D115.2)
A116: Input Headers 1 (J8.4), Diode 1 (D116.2)
A117: Input Headers 1 (J8.5), Diode 1 (D117.2)
A118: Input Headers 1 (J8.6), Diode 1 (D118.2)
A119: Input Headers 1 (J8.7), Diode 1 (D119.2)
A120: Input Headers 1 (J8.8), Diode 1 (D120.2)
A121: Input Headers 1 (J8.9), Diode 1 (D121.2)
A122: Input Headers 1 (J8.10), Diode 1 (D122.2)
A123: Input Headers 1 (J8.11), Diode 1 (D123.2)
A124: Input Headers 1 (J8.12), Diode 1 (D124.2)
A125: Input Headers 1 (J8.13), Diode 1 (D125.2)
A126: Input Headers 1 (J8.14), Diode 1 (D126.2)
A127: Input Headers 1 (J8.15), Diode 1 (D127.2)
A128: Input Headers 1 (J8.16), Diode 1 (D128.2)
A129: Input Headers 1 (J9.1), Diode 1 (D129.2)
A130: Input Headers 1 (J9.2), Diode 1 (D130.2)
A131: Input Headers 1 (J9.3), Diode 1 (D131.2)
A132: Input Headers 1 (J9.4), Diode 1 (D132.2)
A133: Input Headers 1 (J9.5), Diode 1 (D133.2)
A134: Input Headers 1 (J9.6), Diode 1 (D134.2)
A135: Input Headers 1 (J9.7), Diode 1 (D135.2)
A136: Input Headers 1 (J9.8), Diode 1 (D136.2)
A137: Input Headers 1 (J9.9), Diode 1 (D137.2)
A138: Input Headers 1 (J9.10), Diode 1 (D138.2)
A139: Input Headers 1 (J9.11), Diode 1 (D139.2)
A140: Input Headers 1 (J9.12), Diode 1 (D140.2)
A141: Input Headers 1 (J9.13), Diode 1 (D141.2)
A142: Input Headers 1 (J9.14), Diode 1 (D142.2)
A143: Input Headers 1 (J9.15), Diode 1 (D143.2)
A144: Input Headers 1 (J9.16), Diode 1 (D144.2)
A145: Input Headers 2 (J10.1), Diode 1 (D145.2)
A146: Input Headers 2 (J10.2), Diode 1 (D146.2)
A147: Input Headers 2 (J10.3), Diode 1 (D147.2)
A148: Input Headers 2 (J10.4), Diode 1 (D148.2)
A149: Input Headers 2 (J10.5), Diode 1 (D149.2)
A150: Input Headers 2 (J10.6), Diode 1 (D150.2)
A151: Input Headers 2 (J10.7), Diode 1 (D151.2)
A152: Input Headers 2 (J10.8), Diode 1 (D152.2)
A153: Input Headers 2 (J10.9), Diode 1 (D153.2)
A154: Input Headers 2 (J10.10), Diode 1 (D154.2)
A155: Input Headers 2 (J10.11), Diode 1 (D155.2)
A156: Input Headers 2 (J10.12), Diode 1 (D156.2)
A157: Input Headers 2 (J10.13), Diode 1 (D157.2)
A158: Input Headers 2 (J10.14), Diode 1 (D158.2)
A159: Input Headers 2 (J10.15), Diode 1 (D159.2)
A160: Input Headers 2 (J10.16), Diode 1 (D160.2)
A161: Input Headers 2 (J11.1), Diode 2 (D161.2)
A162: Input Headers 2 (J11.2), Diode 2 (D162.2)
A163: Input Headers 2 (J11.3), Diode 2 (D163.2)
A164: Input Headers 2 (J11.4), Diode 2 (D164.2)
A165: Input Headers 2 (J11.5), Diode 2 (D165.2)
A166: Input Headers 2 (J11.6), Diode 2 (D166.2)
A167: Input Headers 2 (J11.7), Diode 2 (D167.2)
A168: Input Headers 2 (J11.8), Diode 2 (D168.2)
A169: Input Headers 2 (J11.9), Diode 2 (D169.2)
A170: Input Headers 2 (J11.10), Diode 2 (D170.2)
A171: Input Headers 2 (J11.11), Diode 2 (D171.2)
A172: Input Headers 2 (J11.12), Diode 2 (D172.2)
A173: Input Headers 2 (J11.13), Diode 2 (D173.2)
A174: Input Headers 2 (J11.14), Diode 2 (D174.2)
A175: Input Headers 2 (J11.15), Diode 2 (D175.2)
A176: Input Headers 2 (J11.16), Diode 2 (D176.2)
A177: Input Headers 2 (J12.1), Diode 2 (D177.2)
A178: Input Headers 2 (J12.2), Diode 2 (D178.2)
A179: Input Headers 2 (J12.3), Diode 2 (D179.2)
A180: Input Headers 2 (J12.4), Diode 2 (D180.2)
A181: Input Headers 2 (J12.5), Diode 2 (D181.2)
A182: Input Headers 2 (J12.6), Diode 2 (D182.2)
A183: Input Headers 2 (J12.7), Diode 2 (D183.2)
A184: Input Headers 2 (J12.8), Diode 2 (D184.2)
A185: Input Headers 2 (J12.9), Diode 2 (D185.2)
A186: Input Headers 2 (J12.10), Diode 2 (D186.2)
A187: Input Headers 2 (J12.11), Diode 2 (D187.2)
A188: Input Headers 2 (J12.12), Diode 2 (D188.2)
A189: Input Headers 2 (J12.13), Diode 2 (D189.2)
A190: Input Headers 2 (J12.14), Diode 2 (D190.2)
A191: Input Headers 2 (J12.15), Diode 2 (D191.2)
A192: Input Headers 2 (J12.16), Diode 2 (D192.2)
A193: Input Headers 2 (J13.1), Diode 2 (D193.2)
A194: Input Headers 2 (J13.2), Diode 2 (D194.2)
A195: Input Headers 2 (J13.3), Diode 2 (D195.2)
A196: Input Headers 2 (J13.4), Diode 2 (D196.2)
A197: Input Headers 2 (J13.5), Diode 2 (D197.2)
A198: Input Headers 2 (J13.6), Diode 2 (D198.2)
A199: Input Headers 2 (J13.7), Diode 2 (D199.2)
A200: Input Headers 2 (J13.8), Diode 2 (D200.2)
A201: Input Headers 2 (J13.9), Diode 2 (D201.2)
A202: Input Headers 2 (J13.10), Diode 2 (D202.2)
A203: Input Headers 2 (J13.11), Diode 2 (D203.2)
A204: Input Headers 2 (J13.12), Diode 2 (D204.2)
A205: Input Headers 2 (J13.13), Diode 2 (D205.2)
A206: Input Headers 2 (J13.14), Diode 2 (D206.2)
A207: Input Headers 2 (J13.15), Diode 2 (D207.2)
A208: Input Headers 2 (J13.16), Diode 2 (D208.2)
A209: Input Headers 2 (J14.1), Diode 2 (D209.2)
A210: Input Headers 2 (J14.2), Diode 2 (D210.2)
A211: Input Headers 2 (J14.3), Diode 2 (D211.2)
A212: Input Headers 2 (J14.4), Diode 2 (D212.2)
A213: Input Headers 2 (J14.5), Diode 2 (D213.2)
A214: Input Headers 2 (J14.6), Diode 2 (D214.2)
A215: Input Headers 2 (J14.7), Diode 2 (D215.2)
A216: Input Headers 2 (J14.8), Diode 2 (D216.2)
A217: Input Headers 2 (J14.9), Diode 2 (D217.2)
A218: Input Headers 2 (J14.10), Diode 2 (D218.2)
A219: Input Headers 2 (J14.11), Diode 2 (D219.2)
A220: Input Headers 2 (J14.12), Diode 2 (D220.2)
A221: Input Headers 2 (J14.13), Diode 2 (D221.2)
A222: Input Headers 2 (J14.14), Diode 2 (D222.2)
A223: Input Headers 2 (J14.15), Diode 2 (D223.2)
A224: Input Headers 2 (J14.16), Diode 2 (D224.2)
A225: Input Headers 2 (J15.1), Diode 2 (D225.2)
A226: Input Headers 2 (J15.2), Diode 2 (D226.2)
A227: Input Headers 2 (J15.3), Diode 2 (D227.2)
A228: Input Headers 2 (J15.4), Diode 2 (D228.2)
A229: Input Headers 2 (J15.5), Diode 2 (D229.2)
A230: Input Headers 2 (J15.6), Diode 2 (D230.2)
A231: Input Headers 2 (J15.7), Diode 2 (D231.2)
A232: Input Headers 2 (J15.8), Diode 2 (D232.2)
A233: Input Headers 2 (J15.9), Diode 2 (D233.2)
A234: Input Headers 2 (J15.10), Diode 2 (D234.2)
A235: Input Headers 2 (J15.11), Diode 2 (D235.2)
A236: Input Headers 2 (J15.12), Diode 2 (D236.2)
A237: Input Headers 2 (J15.13), Diode 2 (D237.2)
A238: Input Headers 2 (J15.14), Diode 2 (D238.2)
A239: Input Headers 2 (J15.15), Diode 2 (D239.2)
A240: Input Headers 2 (J15.16), Diode 2 (D240.2)
A241: Input Headers 2 (J16.1), Diode 2 (D241.2)
A242: Input Headers 2 (J16.2), Diode 2 (D242.2)
A243: Input Headers 2 (J16.3), Diode 2 (D243.2)
A244: Input Headers 2 (J16.4), Diode 2 (D244.2)
A245: Input Headers 2 (J16.5), Diode 2 (D245.2)
A246: Input Headers 2 (J16.6), Diode 2 (D246.2)
A247: Input Headers 2 (J16.7), Diode 2 (D247.2)
A248: Input Headers 2 (J16.8), Diode 2 (D248.2)
A249: Input Headers 2 (J16.9), Diode 2 (D249.2)
A250: Input Headers 2 (J16.10), Diode 2 (D250.2)
A251: Input Headers 2 (J16.11), Diode 2 (D251.2)
A252: Input Headers 2 (J16.12), Diode 2 (D252.2)
A253: Input Headers 2 (J16.13), Diode 2 (D253.2)
A254: Input Headers 2 (J16.14), Diode 2 (D254.2)
A255: Input Headers 2 (J16.15), Diode 2 (D255.2)
A256: Input Headers 2 (J16.16), Diode 2 (D256.2)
